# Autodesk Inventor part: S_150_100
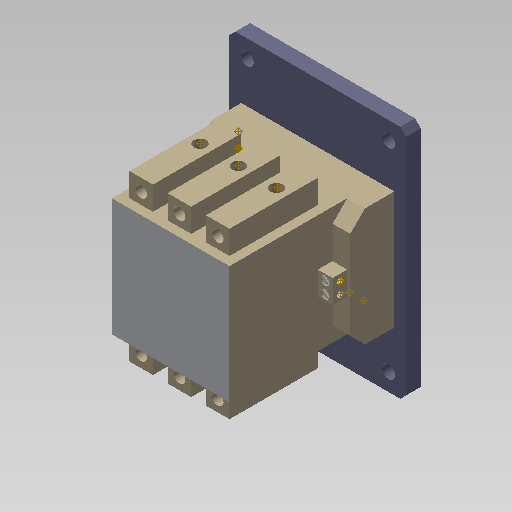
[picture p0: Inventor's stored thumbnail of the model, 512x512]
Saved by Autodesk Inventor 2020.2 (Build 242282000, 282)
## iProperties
GlobalPropertyList: <PropertyList/>
Manager: www.cadconsulting.pl
Company: Fabian Stasiak CAD Consulting
Created: 2014-09
Part Number: S_150_100
Material: Ogólny
Document SubType Name: Modeling
Designer: F.Stasiak
Density: 1 g/cm^3
Appearance: Domyślna
Catalog Web Link: www.expertbooks.pl
Author: F.Stasiak
Subject: Zbiór ćwiczeń. Autodesk Inventor 2020. Kurs Professional
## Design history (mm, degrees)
sketch "Szkic1"
  geometry: L1 (-30, 40)-(30, 40); L2 (30, 40)-(30, -40); L3 (30, -40)-(-30, -40); L4 (-30, -40)-(-30, 40); L5 (-30, 40)-(30, -40); L6 (30, 40)-(-30, -40); 1 further point
  constraints: 12 end point, 2 midpoint, 2 parallel, 1 horizontal, 1 perpendicular
  dimensions: "d0" = 60 distance of L2.end L3.end; "d1" = 80 distance of L1.end L2.end
extrude "Wyciągnięcie proste1" new body sketch "Szkic1" distance "d2" = 5; taper "d3" = 0 deg
sketch "Szkic2"
  geometry: L1 (-20, 20)-(20, 20); L2 (20, 20)-(20, -20); L3 (20, -20)-(-20, -20); L4 (-20, -20)-(-20, 20); L5 (-20, 20)-(20, -20); L6 (20, 20)-(-20, -20); 1 further point
  constraints: 12 end point, 2 midpoint, 2 parallel, 1 horizontal, 1 perpendicular
  dimensions: "d4" = 40 distance of L2.end L3.end; "d5" = 40 distance of L1.end L2.end
extrude "Wyciągnięcie proste2" join sketch "Szkic2" distance "d6" = 50; taper "d7" = 0 deg
sketch "Szkic3"
  geometry: L1 (3, 17)-(11, 17); L2 (11, 17)-(11, 47); L3 (11, 47)-(3, 47); L4 (3, 47)-(3, 17); L5 (16, 17)-(24, 17); L6 (24, 17)-(24, 47); L7 (24, 47)-(16, 47); L8 (16, 47)-(16, 17); L9 (29, 17)-(37, 17); L10 (37, 17)-(37, 47); L11 (37, 47)-(29, 47); L12 (29, 47)-(29, 17); L13 (0, 0)-(0, 50) reference; L14 (40, 0)-(40, 50) reference; L15 (0, 50)-(40, 50) reference; C1 r 2.125 at (7, 27); C2 r 2.125 at (20, 27); C3 r 2.125 at (33, 27); 5 further points
  constraints: 24 end point, 6 parallel, 4 midpoint, 4 point on line, 4 vertical alignment, 3 centre point, 3 horizontal, 3 perpendicular, 2 collinear, 2 equal radius, 2 horizontal alignment
  dimensions: "d8" = 30 distance of L3.end L1.start; "d9" = 3 distance between parallel lines of L13 L4; "d10" = 8 distance of L2.end L3.end; "d11" = 3 distance between parallel lines of L10 L14 (= d9); "d12" = 3 distance between parallel lines of L15 L11 (= d11); "d13" = 4.25 diameter of C1; "d14" = 10 distance from line of C1.centre L1
extrude "Wyciągnięcie proste3" join sketch "Szkic3" distance "d15" = 8; taper "d16" = 0 deg
sketch "Szkic4"
  geometry: L1 (0, 0)-(0, -8) reference; L2 (8, -8)-(0, -8) reference; L3 (21, -8)-(13, -8) reference; L4 (34, -8)-(26, -8) reference; C1 r 2 at (4, -4); C2 r 2 at (17, -4); C3 r 2 at (30, -4); 7 further points
  constraints: 6 midpoint, 3 centre point, 3 horizontal alignment, 3 vertical alignment, 2 equal radius
  dimensions: "d17" = 4 diameter of C1
extrude "Wyciągnięcie proste4" cut sketch "Szkic4" distance "d18" = 20; taper "d19" = 0 deg
sketch "Szkic5"
  geometry: L1 (20, 20)-(20, -20) reference; L2 (20, -20)-(-20, -20) reference; L3 (-20, -20)-(-20, 20) reference; L4 (-20, 20)-(20, 20) reference; L5 (30, 40)-(-30, 40) reference; L6 (-30, 40)-(-30, -40) reference; L7 (-30, -40)-(30, -40) reference; L8 (30, -40)-(30, 40) reference; L9 (20, -20)-(26, -20); L10 (20, 20)-(26, 20); L11 (30, -40)-(30, 40) reference; L12 (26, -20)-(26, 20); 3 further points
  constraints: 6 end point, 2 perpendicular, 2 point on line, 1 horizontal
  dimensions: "d42" = 6 distance between parallel lines of L1 L12
extrude "Wyciągnięcie proste5" join sketch "Szkic5" distance "d20" = 15; taper "d21" = 0 deg
chamfer "Faza1" distance "d22" = 5; stored, may be unused: second distance "d23" = 2, angle "d24" = 45 deg
derived "Z_02.ipt"
feature "Przesuń bryłę1"
chamfer "Faza2" distance "d30" = 2; stored, may be unused: second distance "d31" = 2, angle "d32" = 45 deg
mirror "Odbicie lustrzane1"
sketch "Szkic6"
  geometry: L1 (-24, -34)-(24, -34); L2 (24, -34)-(24, 34); L3 (24, 34)-(-24, 34); L4 (-24, 34)-(-24, -34); L5 (-24, -34)-(24, 34); L6 (24, -34)-(-24, 34); 1 further point
  constraints: 12 end point, 2 midpoint, 2 parallel, 1 horizontal, 1 perpendicular
  dimensions: "d33" = 48 distance of L3.end L2.end; "d34" = 68 distance of L2.end L1.end
hole "Otwór1" sketch "Szkic6" at (-24, 34), (24, 34), (24, -34), (-24, -34) diameter "d35" = 4.5; stored, may be unused: countersink angle "d39" = 90 deg, drill point angle "d41" = 118 deg; dims "d36" = 6, "d37" = 4, "d38" = 2, "d40" = 8
mirror "Odbicie lustrzane2"
feature "Utwórz kombinację1"
  node "Bryła2"
node "Płaszczyzna konstrukcyjna1"
node "Oś konstrukcyjna1"
node "Punkt konstrukcyjny9"
  node "Płaszczyzna konstrukcyjna2"
node "Punkt konstrukcyjny10"
node "Płaszczyzna konstrukcyjna3"
node "Płaszczyzna konstrukcyjna4"
node "Punkt konstrukcyjny11"
node "Punkt konstrukcyjny12"
node "Płaszczyzna konstrukcyjna5"
node "Płaszczyzna konstrukcyjna6"
node "Płaszczyzna konstrukcyjna8"
node "Płaszczyzna konstrukcyjna7"
node "Punkt konstrukcyjny13"
node "Punkt konstrukcyjny14"
sketch "Szkic7"
  geometry: C1 r 1 at (-2.5, 2) reference
node "A1"
sketch "Szkic8"
  geometry: C1 r 1 at (-2.5, 6) reference
node "A2"
sketch "Szkic9"
  geometry: C1 r 2.125 at (33, 27) reference
node "1"
sketch "Szkic10"
  geometry: C1 r 2.125 at (4, -10) reference
node "2"
sketch "Szkic11"
  geometry: C1 r 2.125 at (20, 27) reference
node "3"
sketch "Szkic12"
  geometry: C1 r 2.125 at (4, -10) reference
node "4"
sketch "Szkic13"
  geometry: C1 r 2.125 at (7, 27) reference
node "5"
sketch "Szkic14"
  geometry: C1 r 2.125 at (4, -10) reference
node "6"
node "Bryła1"
node "Pętla rzutowana1"
feature "Bryła1::Z_02.ipt" dims "d25" = 10
tag "Bryła wyprowadzona1"
other parameters: "d26" = 90 deg, "d27" = 22.5, "d28" = 0, "d43" = 5, "d44" = 5, "d45" = 5, "d46" = 5, "d47" = 3, "d48" = 5
